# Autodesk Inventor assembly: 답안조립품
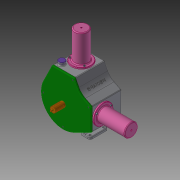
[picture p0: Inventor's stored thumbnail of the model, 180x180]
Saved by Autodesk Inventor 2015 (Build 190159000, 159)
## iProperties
Created: 2022-01
Part Number: 답안조립품
Document SubType Name: Assembly
Designer: user
Mass: 3748.67 g
Surface Area: 4101.75 cm^2
Volume: 1119.43 cm^3
Density: 3.34872 g/cm^3
Author: user
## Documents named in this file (13)
- C:\Users\user\Desktop\620117V1006\답안조립품.iam
- C:\Users\user\Desktop\620117V1006\너트 M3.ipt
- C:\Users\user\Desktop\620117V1006\베어링 20 x 37 x 9.ipt
- C:\Users\user\Desktop\620117V1006\본체.ipt
- C:\Users\user\Desktop\620117V1006\볼트 M3 x 12.ipt
- C:\Users\user\Desktop\620117V1006\실린더.ipt
- C:\Users\user\Desktop\620117V1006\앞커버.ipt
- C:\Users\user\Desktop\620117V1006\축.ipt
- C:\Users\user\Desktop\620117V1006\측정게이지.ipt
- C:\Users\user\Desktop\620117V1006\커넥팅로드 캡.ipt
- C:\Users\user\Desktop\620117V1006\커넥팅로드.ipt
- C:\Users\user\Desktop\620117V1006\피스톤 핀.ipt
- C:\Users\user\Desktop\620117V1006\피스톤.ipt
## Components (4 placed, 2 different names)
1. 피스톤 핀:1
2. 피스톤:1
3. 피스톤:2
4. 피스톤 핀:2
